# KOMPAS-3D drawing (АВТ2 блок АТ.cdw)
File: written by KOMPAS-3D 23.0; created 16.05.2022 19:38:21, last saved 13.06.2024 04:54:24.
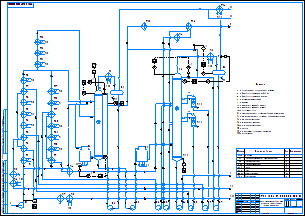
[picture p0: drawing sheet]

Sheet 1: A1, landscape

Document properties: Автор: 79870418100; Полное имя файла: G:\Учёба\схемы\АТ АВТ2\Для публикации\АВТ2 АТ АСУТП.cdw; Литера: У

Title block, sheet 1: Наименование: Блок АТ установки АВТ / Схема комбинированная / принципиальная; designation: УТЭК 18.02.09.ПП.00.00.000.С3; Количество листов документа: 1; cell 10: КИПиА; Форматы листов документа: A1; stored path: C:\Users\79870\Desktop\Ахметнабиев.cdw

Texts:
  Normal
  Обознач.
  Кол.
  Емкость
  Колонна частичного отбензинивания
  Колонна основная
  Колонна отпарная
  Насос
  Печь
  Теплообменник
  Холодильник
  VII
  XIV
  VIII
  XII
  XVI
  TRC
  PIA
  LRCA
  PRCA
  Потоки
  Обезвоженная, обессоленная нефть
  Углеводородный газ на УСРПГ
  III
  Углеводородный газ на печи
  Нестабильный бензин
  Мазут
  Дизельное топливо зимнее
  Дизельное топливо летнее
  Оборотная вода
  I Циркуляционное орошение вакуумной колонны
  II Циркуляционное орошение вакуумной колонны
  II Масляная фракция
  III Масляная фракция
  XIII
  IV Масляная фракция
  Гудрон
  В закрытую дренажную систему
  Водяной пар
Dimensions and other numbers on the sheet: 2; 1; 9; 21; 8; 1-1; 2-1; 2-3; 2-2; 5-1; 5; 4-1; 4; 4-2; 4-3; 10-1; 10; 9-1; 9-2; 9-3; 3-1; 3; 3-2; 3-3; 6-1; 6; 6-2; 6-3; 7-1; 7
